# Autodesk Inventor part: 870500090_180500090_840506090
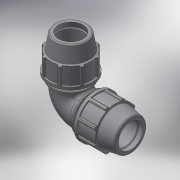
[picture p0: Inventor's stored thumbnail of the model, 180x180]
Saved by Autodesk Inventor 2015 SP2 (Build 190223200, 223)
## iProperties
Created: 2017-02
Part Number: 870500090_180500090_840506090
Material: Generic
Description: PLASSON 90° ELBOW 90-90
Document SubType Name: Modeling
Designer: KIM
Mass: 1923.39 g
Surface Area: 2516.77 cm^2
Volume: 1923.39 cm^3
Density: 1 g/cm^3
Appearance: Default
Author: KIM
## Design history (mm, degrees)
derived "87050.ipt"
feature "Solid1::87050.ipt"
tag "TaggingFeature1"
body "Solid1"
other parameters: "d4" = 18, "d5" = 54, "d7" = 152, "d9" = 30.85714, "d11" = 7.2, "d13" = 120 deg, "d14" = 117, "d15" = 10 deg, "d16" = 132.24, "d18" = 4.5, "d19" = 35 deg, "d20" = 17.5 deg, "d21" = 141.36, "d23" = 0, "d25" = 360 deg, "d27" = 3.04, "d33" = 1.8, "d42" = 73.44, "d43" = 4.56, "d46" = 2.7, "d51" = 216, "d59" = 90 deg, "d63" = 161, "d64" = 81, "d67" = 114, "d68" = 12.96, "d70" = 90 deg, "d71" = 13.5, "d72" = 10.13333, "d73" = 0, "d75" = 90 deg, "d77" = 129.5952, "d78" = 4.32, "E_" = 152, "A_" = 216, "l_" = 161
